Omron CX-Programmer project NewProject (CX-Programmer 7.03)

# PLC cj_ethernet: CJ1M CPU11
I/O table (CPU CJ1M-CPU11): rack 0 slot 0 CJ1W-ETN21(ETN21Mode); rack 0 slot 1 CJ1W-ID211; rack 0 slot 2 CJ1W-OC211; rack 0 slot 3 CJ1W-MAD42; rack 0 slot 4 CJ1W-ETN21(ETN21Mode)

## Program Ethernet_Email (cyclic task 0)
Local symbols
Button 75.00 BOOL  ; Button or Work Bit
Email_Now 50.00 BOOL  ; E-mail Now
reset 60.00 BOOL  ; reset counter

### Section Email

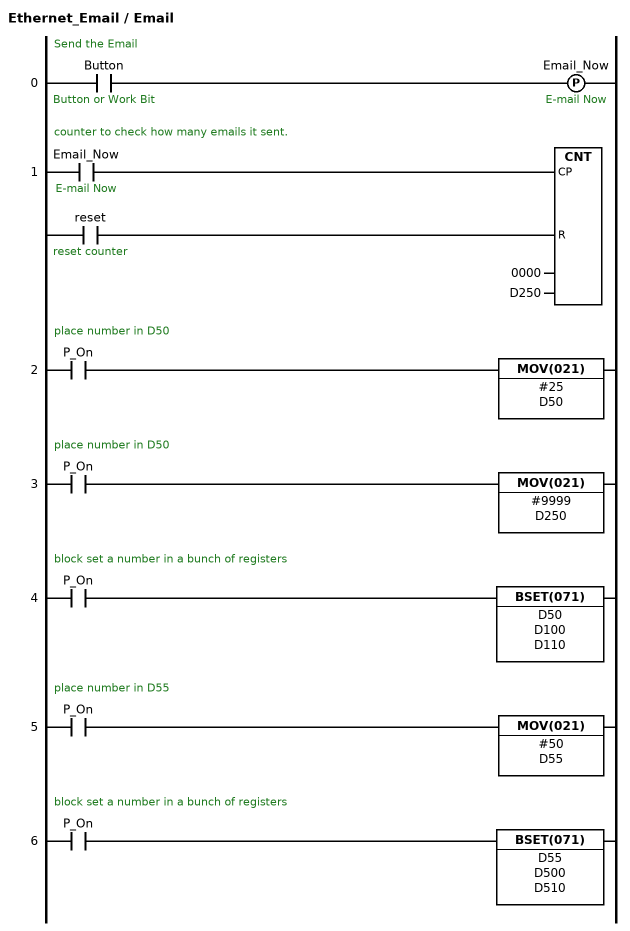
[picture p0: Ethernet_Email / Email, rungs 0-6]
; rung 0: Send the Email
LD Button  ; Button or Work Bit
DIFU(013) Email_Now  ; E-mail Now
; rung 1: counter to check how many emails it sent.
LD Email_Now  ; E-mail Now
LD reset  ; reset counter
CNT 0000 D250
; rung 2: place number in D50
LD P_On
MOV(021) #25 D50
; rung 3: place number in D50
LD P_On
MOV(021) #9999 D250
; rung 4: block set a number in a bunch of registers
LD P_On
BSET(071) D50 D100 D110
; rung 5: place number in D55
LD P_On
MOV(021) #50 D55
; rung 6: block set a number in a bunch of registers
LD P_On
BSET(071) D55 D500 D510

### Section END
; rung 0
END(001)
